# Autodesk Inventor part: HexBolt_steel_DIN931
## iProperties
Author: Jørgen Albe Bjørnes
Shininess: 25.0
PropertySet Name: _Private Model Information
Created: 2001-01
Part Number: HexBolt_steel_DIN931
Document SubType Name: Modeling
Designer: Jørgen Albe Bjørnes
Material: 8.8
Description: Hex-head bolt M8x40
Vendor: DIN 931 / DIN EN 24 014
Control State: 0
Master: False
Checked Out: False
PropertySet Name: Design Tracking Control
Density: 0.0
Volumn: 0.0
Area: 0.0
PropertySet Name: Model Information
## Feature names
1. Extrusion1
2. Extrusion2
3. Revolution2
4. Chamfer1
5. Extrusion3
